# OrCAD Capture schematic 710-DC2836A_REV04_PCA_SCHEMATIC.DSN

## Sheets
1 PAGE3
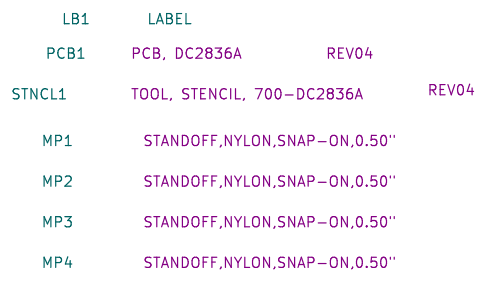
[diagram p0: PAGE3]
2 PAGE1: size Custom; title: SWITCHER WITH DIGITAL POWER SYSTEM MANAGEMENT; company: ANALOG DEVICES; note: DEMO BOARD BILL OF MATERIALS; note: DUAL 6A 20V POLYPHASE MONOLITHIC STEP-DOWN SILENT
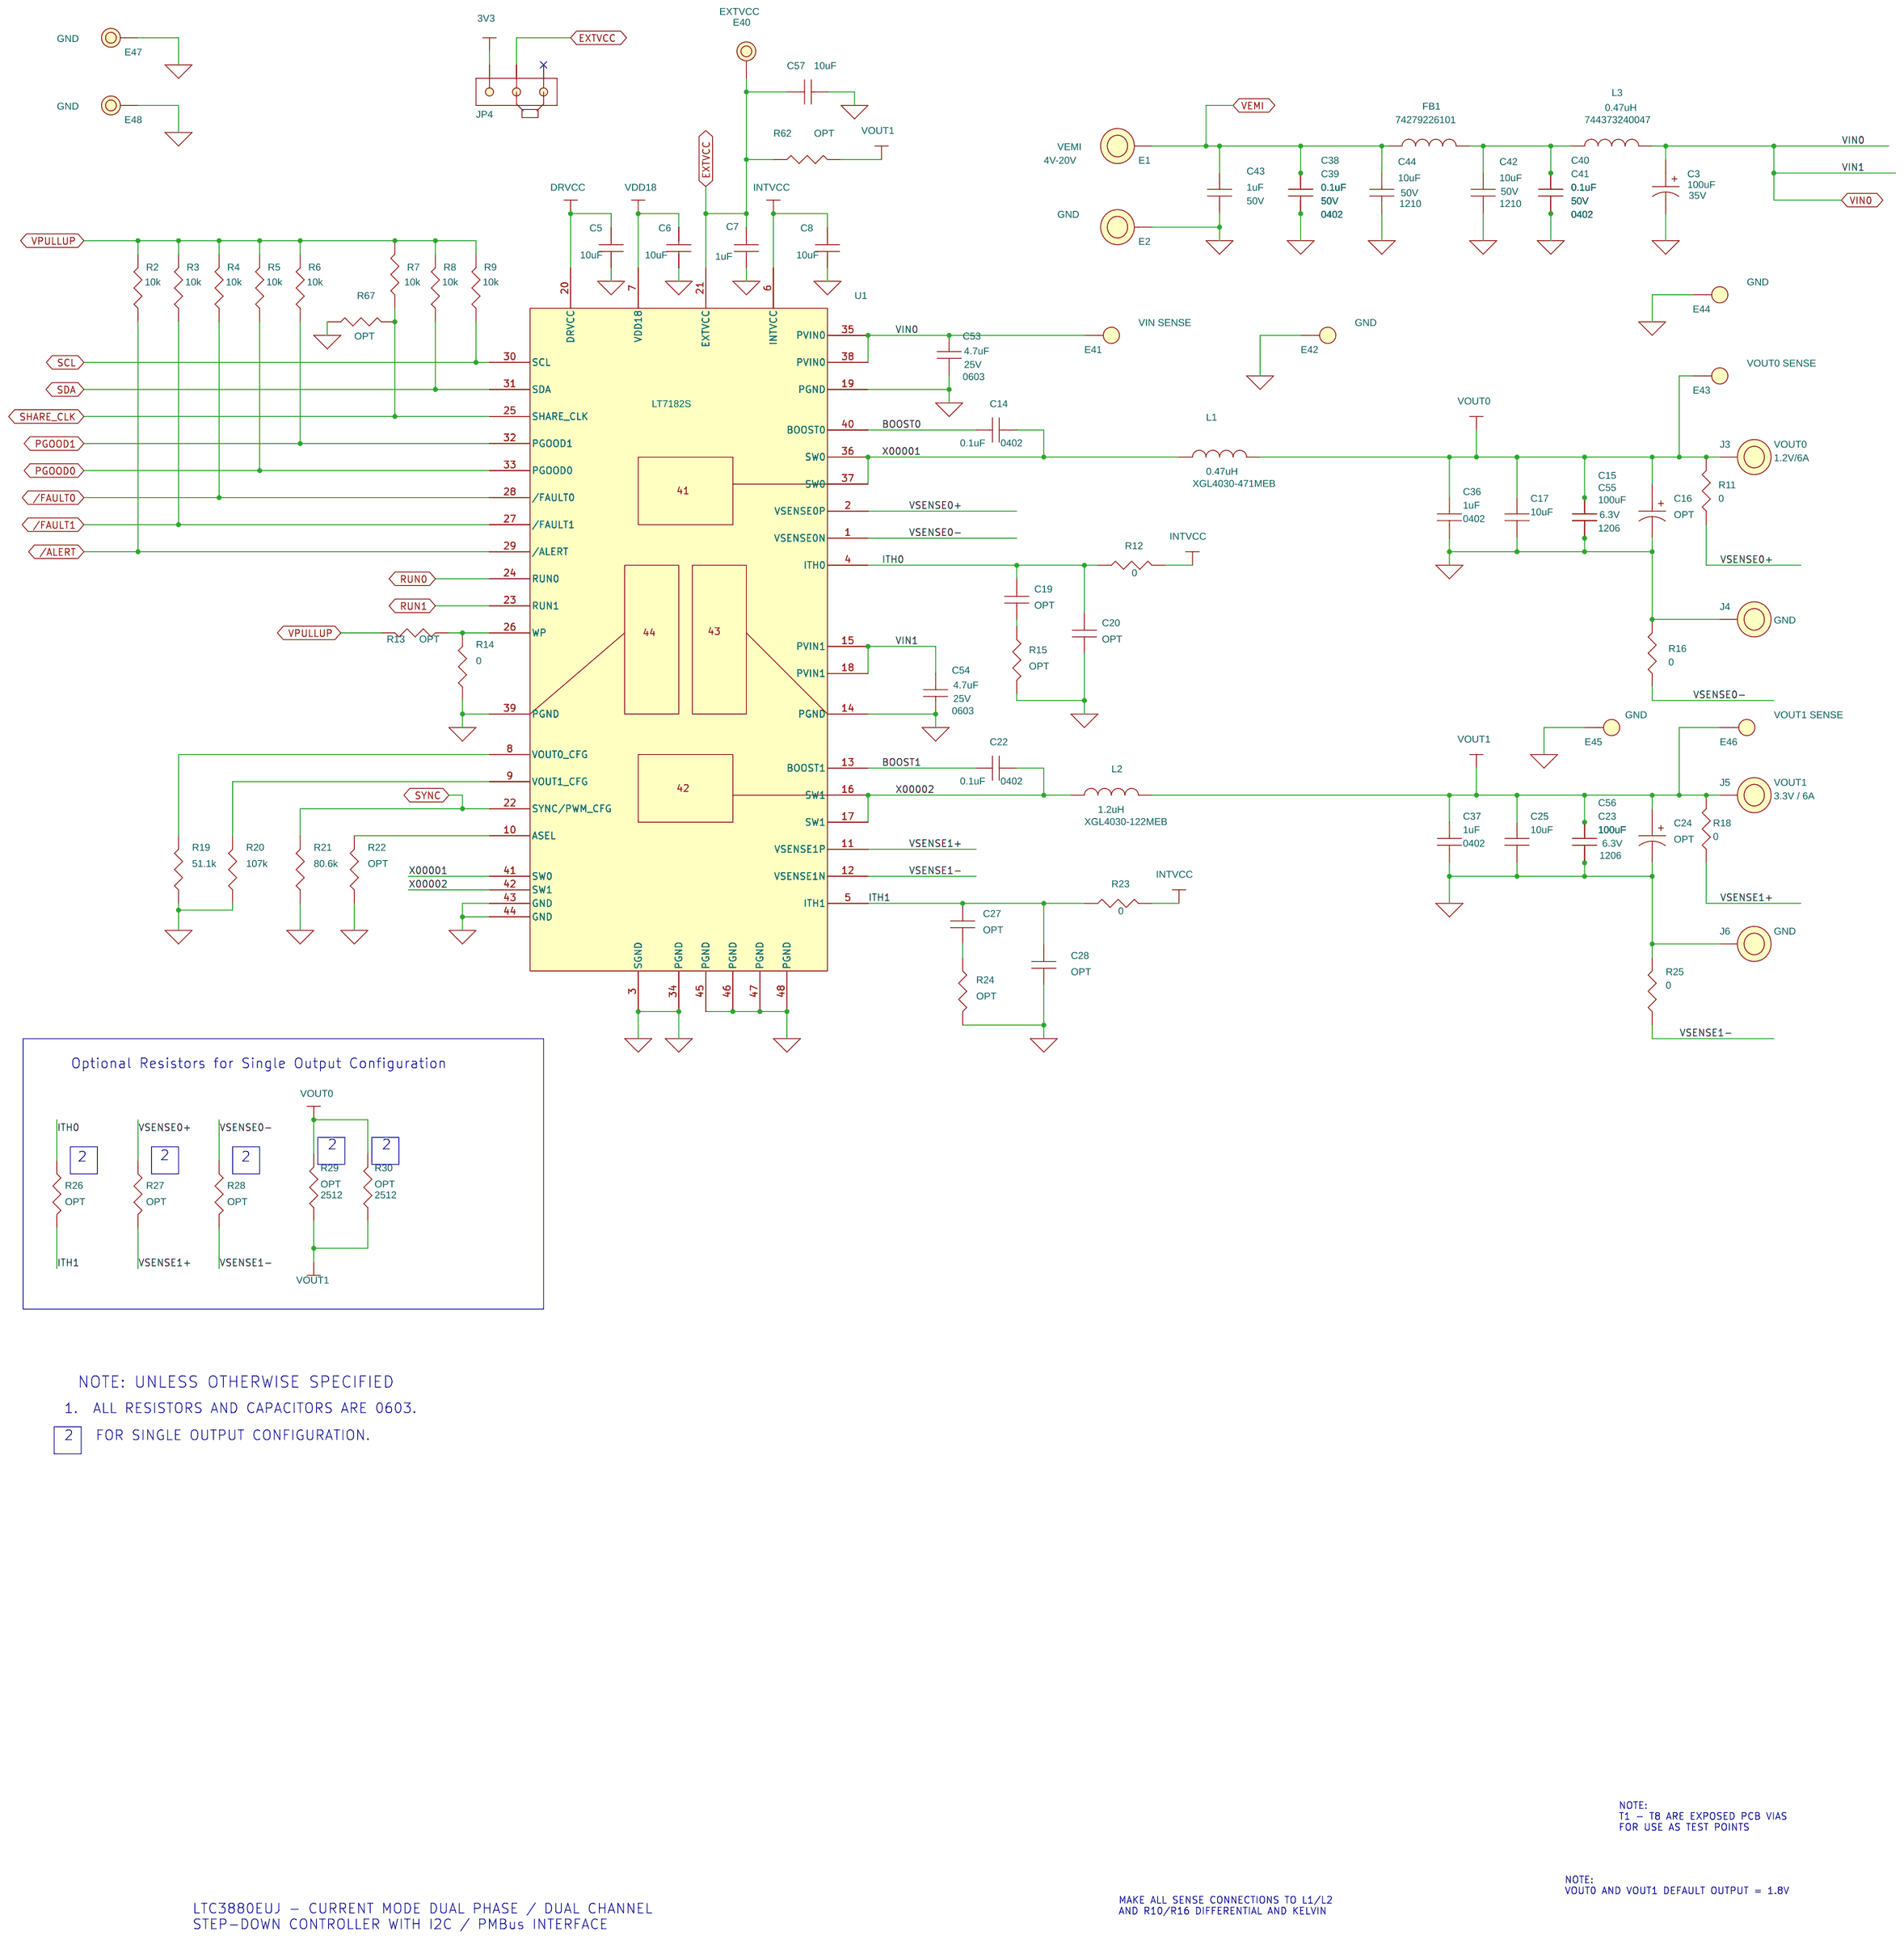
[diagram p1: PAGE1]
3 PAGE2: size Custom; title: SWITCHER WITH DIGITAL POWER SYSTEM MANAGEMENT; company: ANALOG DEVICES; note: DEMO BOARD BILL OF MATERIALS; note: DUAL 6A 20V POLYPHASE MONOLITHIC STEP-DOWN SILENT
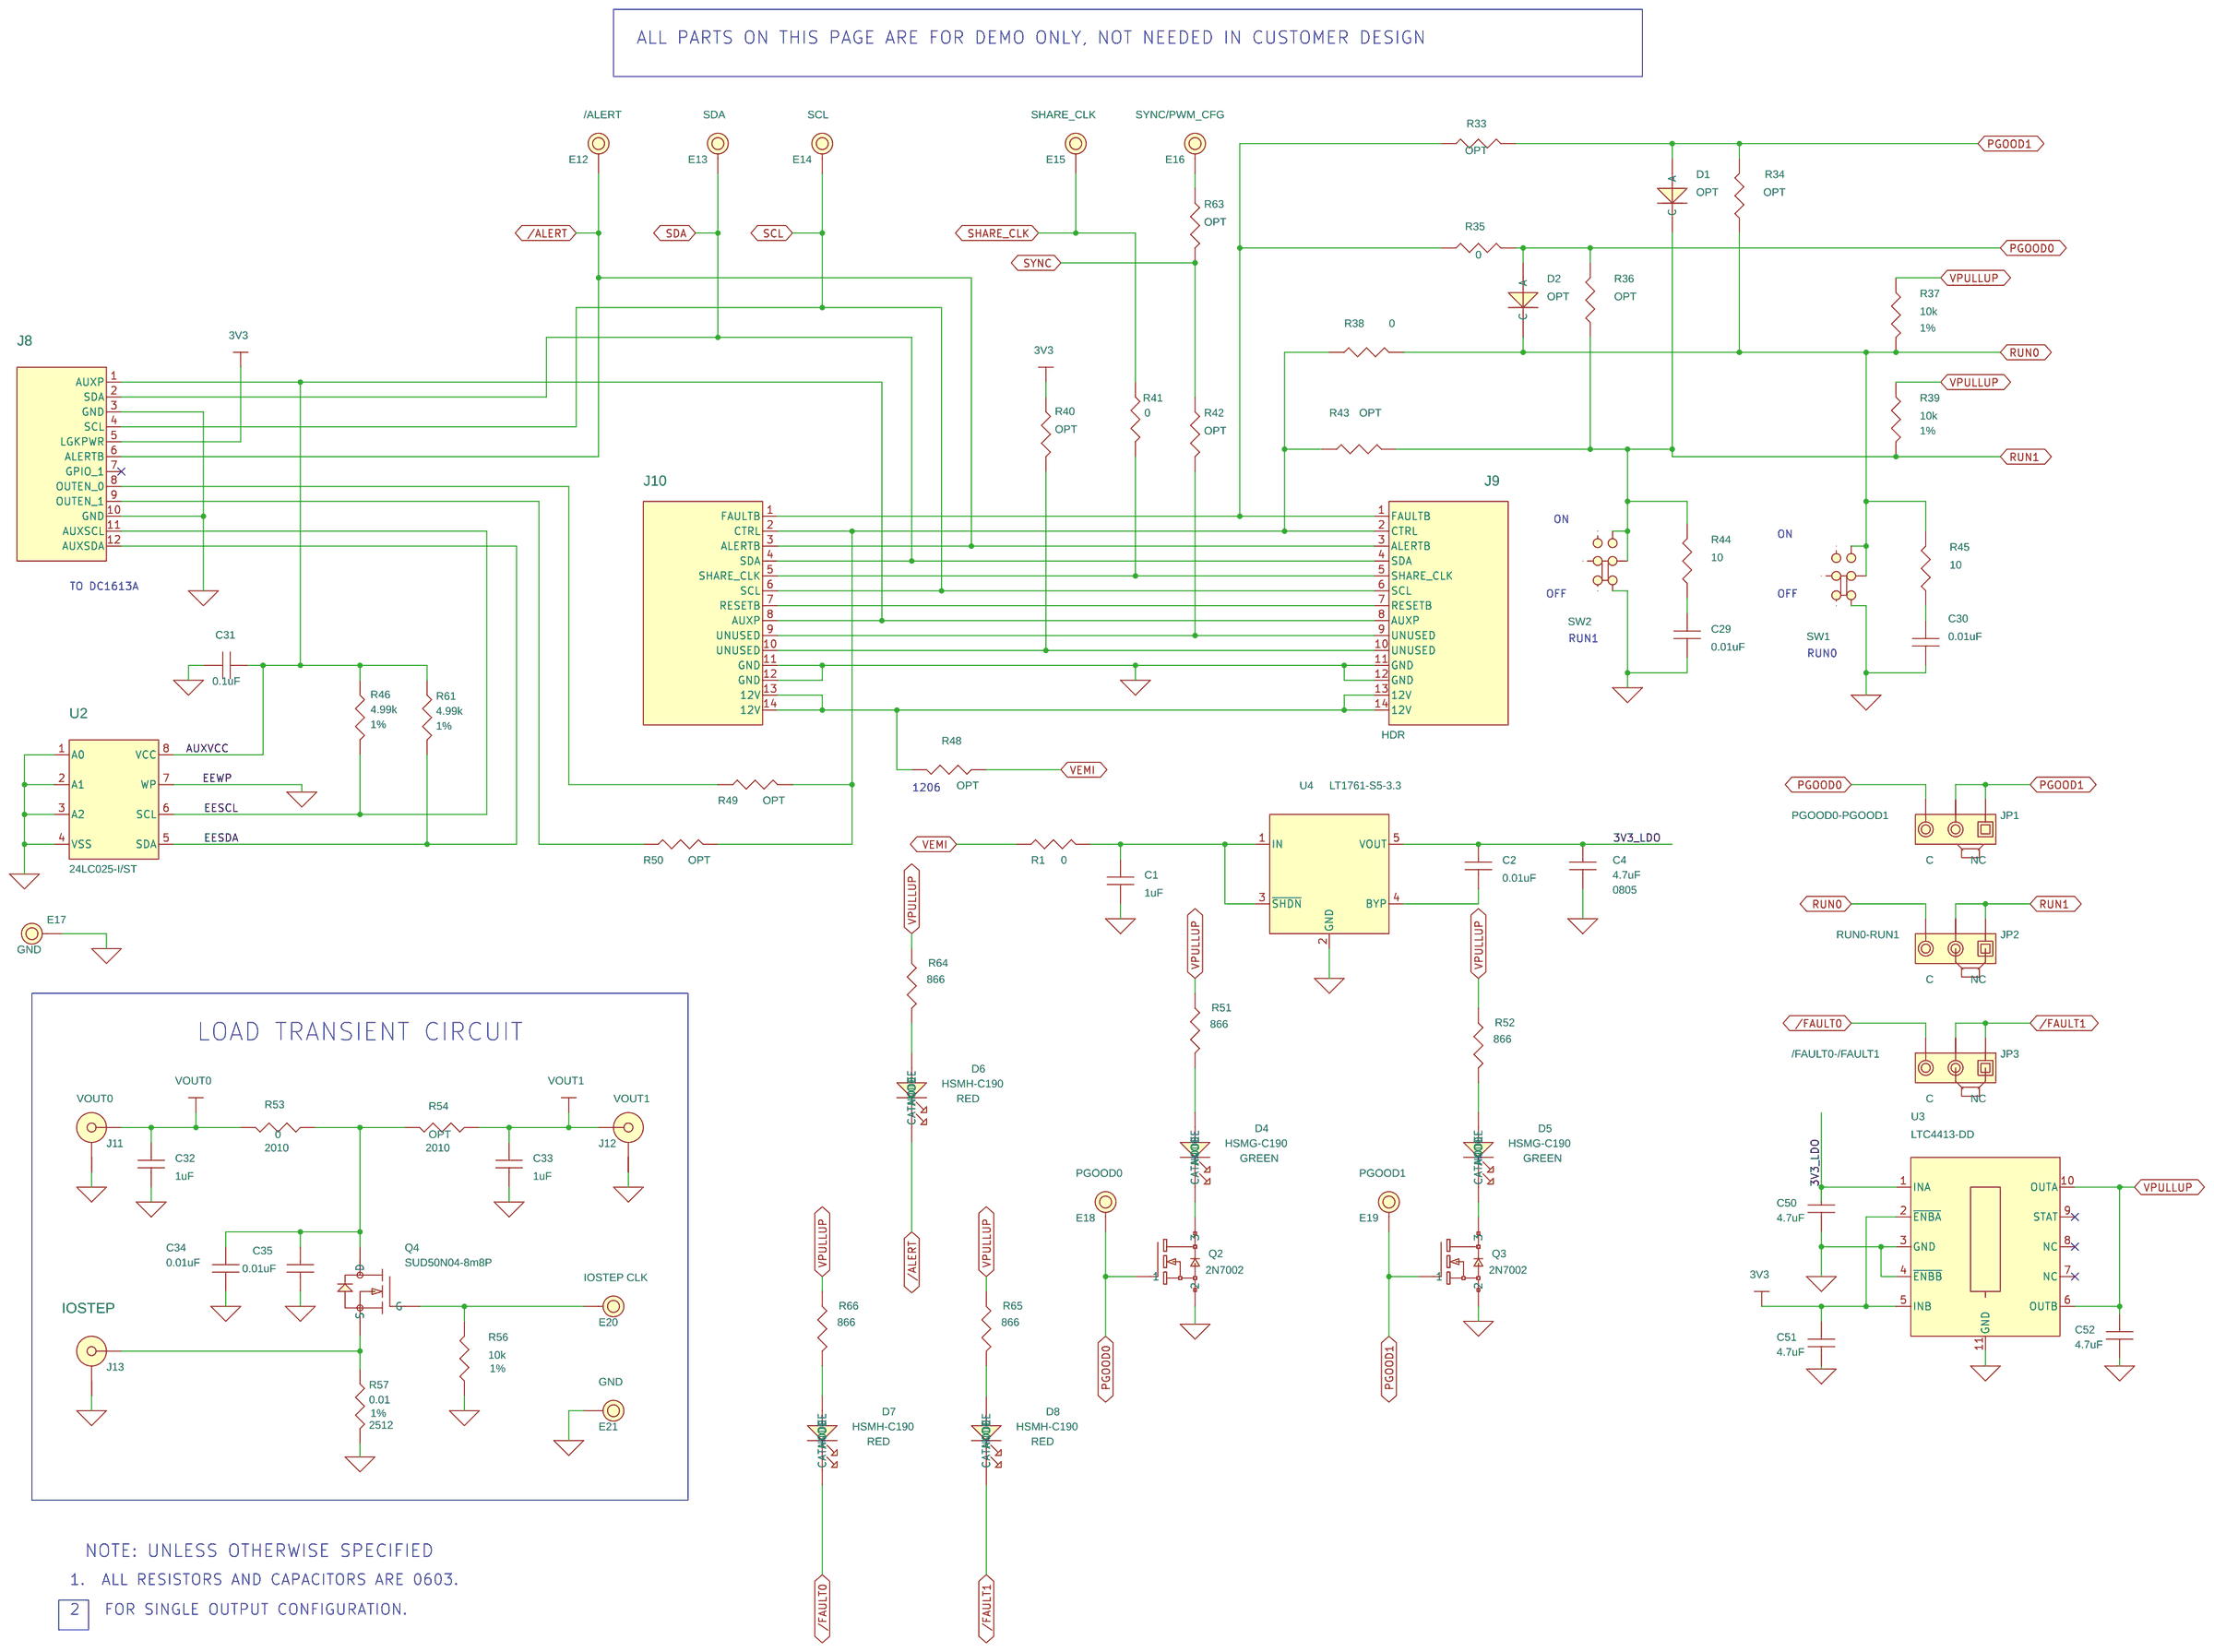
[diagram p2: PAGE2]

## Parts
sheet PAGE1
C3  100uF  [PANASONIC_ZK_6.3X7.7]
C5  10uF  [CC0603N]
C6  10uF  [CC0603N]
C7  1uF  [CC0603N]
C8  10uF  [CC0603N]
C14  0.1uF  [CC0402N]
C15  100uF  [CC1206N]
C16  OPT  [CAPMP7343N]
C17  10uF  [CC0603N]
C19  OPT  [CC0603N]
C20  OPT  [CC0603N]
C22  0.1uF  [CC0402N]
C23  100uF  [CC1206N]
C24  OPT  [CAPMP7343N]
C25  10uF  [CC0603N]
C27  OPT  [CC0603N]
C28  OPT  [CC0603N]
C36  1uF  [CC0402N]
C37  1uF  [CC0402N]
C38  0.1uF  [CC0402N]
C39  0.1uF  [CC0402N]
C40  0.1uF  [CC0402N]
C41  0.1uF  [CC0402N]
C42  10uF  [CC1210N]
C43  1uF  [CC0603N]
C44  10uF  [CC1210N]
C53  4.7uF  [CC0603N]
C54  4.7uF  [CC0603N]
C55  100uF  [CC1206N]
C56  100uF  [CC1206N]
C57  10uF  [CC0603N]
E1  BANANA JACK  [KEY-575-4]
E2  BANANA JACK  [KEY-575-4]
E40  TEST POINT  [MILLMAX2501]
E41  TEST POINT  [MILLMAX2308]
E42  TEST POINT  [MILLMAX2308]
E43  TEST POINT  [MILLMAX2308]
E44  TEST POINT  [MILLMAX2308]
E45  TEST POINT  [MILLMAX2308]
E46  TEST POINT  [MILLMAX2308]
E47  TEST POINT  [MILLMAX2501]
E48  TEST POINT  [MILLMAX2501]
FB1  100 OHMS@100MHz  [WURTH-74279226101]
J3  BANANA JACK  [KEY-575-4]
J4  BANANA JACK  [KEY-575-4]
J5  BANANA JACK  [KEY-575-4]
J6  BANANA JACK  [KEY-575-4]
JP4  HDR  [HD1X3-079]
L1  0.47uH  [COILCRAFT-XGL4030]
L2  1.2uH  [COILCRAFT-XGL4030]
L3  0.47uH  [WURTH-4020]
R2  10k  [CR0603N]
R3  10k  [CR0603N]
R4  10k  [CR0603N]
R5  10k  [CR0603N]
R6  10k  [CR0603N]
R7  10k  [CR0603N]
R8  10k  [CR0603N]
R9  10k  [CR0603N]
R11  0  [CR0603N]
R12  0  [CR0603N]
R13  OPT  [CR0603N]
R14  0  [CR0603N]
R15  OPT  [CR0603N]
R16  0  [CR0603N]
R18  0  [CR0603N]
R19  51.1k  [CR0603N]
R20  107k  [CR0603N]
R21  80.6k  [CR0603N]
R22  OPT  [CR0603N]
R23  0  [CR0603N]
R24  OPT  [CR0603N]
R25  0  [CR0603N]
R26  OPT  [CR0603N]
R27  OPT  [CR0603N]
R28  OPT  [CR0603N]
R29  OPT  [CR2512N]
R30  OPT  [CR2512N]
R62  OPT  [CR0603N]
R67  OPT  [CR0603N]
U1  LT7182S  [LTC-LQFN-40-1607]
XJP4  SHUNT
sheet PAGE2
C1  1uF  [CC0603N]
C2  0.01uF  [CC0603N]
C4  4.7uF  [CC0805N]
C29  0.01uF  [CC0603N]
C30  0.01uF  [CC0603N]
C31  0.1uF  [CC0603N]
C32  1uF  [CC0603N]
C33  1uF  [CC0603N]
C34  0.01uF  [CC0603N]
C35  0.01uF  [CC0603N]
C50  4.7uF  [CC0603N]
C51  4.7uF  [CC0603N]
C52  4.7uF  [CC0603N]
D1  OPT  [SOD-323N]
D2  OPT  [SOD-323N]
D4  GREEN  [LED_0603]
D5  GREEN  [LED_0603]
D6  RED  [LED_0603]
D7  RED  [LED_0603]
D8  RED  [LED_0603]
E12  TEST POINT  [MILLMAX2501]
E13  TEST POINT  [MILLMAX2501]
E14  TEST POINT  [MILLMAX2501]
E15  TEST POINT  [MILLMAX2501]
E16  TEST POINT  [MILLMAX2501]
E17  TEST POINT  [MILLMAX2501]
E18  TEST POINT  [MILLMAX2501]
E19  TEST POINT  [MILLMAX2501]
E20  TEST POINT  [MILLMAX2501]
E21  TEST POINT  [MILLMAX2501]
J8  HDR,SHROUDED  [HD2X6-079-MOLEX]
J9  HDR  [MOLEX-0877601416]
J10  HDR  [SULLINS-NPPN072FJFN-RC]
J11  RF,BNC  [CONNEX-112404]
J12  RF,BNC  [CONNEX-112404]
J13  RF,BNC  [CONNEX-112404]
JP1  HDR  [HD1X3-079]
JP2  HDR  [HD1X3-079]
JP3  HDR  [HD1X3-079]
Q2  2N7002  [SOT23-3N]
Q3  2N7002  [SOT23-3N]
Q4  SUD50N04-8m8P  [TO-252-3N]
R1  0  [CR0603N]
R33  OPT  [CR0603N]
R34  OPT  [CR0603N]
R35  0  [CR0603N]
R36  OPT  [CR0603N]
R37  10k  [CR0603N]
R38  0  [CR0603N]
R39  10k  [CR0603N]
R40  OPT  [CR0603N]
R41  0  [CR0603N]
R42  OPT  [CR0603N]
R43  OPT  [CR0603N]
R44  10  [CR0603N]
R45  10  [CR0603N]
R46  4.99k  [CR0603N]
R48  OPT  [CR1206N]
R49  OPT  [CR0603N]
R50  OPT  [CR0603N]
R51  866  [CR0603N]
R52  866  [CR0603N]
R53  0  [CR2010N]
R54  OPT  [CR2010N]
R56  10k  [CR0603N]
R57  0.01  [VISHAY-WSL2512-T30]
R61  4.99k  [CR0603N]
R63  OPT  [CR0603N]
R64  866  [CR0603N]
R65  866  [CR0603N]
R66  866  [CR0603N]
SW1  DPDT  [CK-JS202011CQN]
SW2  DPDT  [CK-JS202011CQN]
U2  24LC025-I/ST  [MICROCHIP-TSSOP-8]
U3  LTC4413-DD  [LTC-DD-10-1699]
U4  LT1761-S5-3.3  [LTC-S5-5-1635]
XJP1  SHUNT
XJP2  SHUNT
XJP3  SHUNT
sheet PAGE3
LB1  LABEL  [895-0154_REV01]
MP1  STANDOFF  [KEYSTONE_8829-8834]
MP2  STANDOFF  [KEYSTONE_8829-8834]
MP3  STANDOFF  [KEYSTONE_8829-8834]
MP4  STANDOFF  [KEYSTONE_8829-8834]
PCB1  PCB, DC2836A
STNCL1  TOOL, STENCIL, 700-DC2836A

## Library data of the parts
C3 = CAP_P: CAP.,100uF,ALUM,35V,20%,SMD,AEC-Q200; CLASS: DISCRETE; Dielectric Type: ALUM; Inventory Qty: 0; Manufacturer: PANASONIC; Manufacturer PN: EEHZK1V101XP; PART_NUMBER: 150-1440; Package Size: SMD; Part Number: PANASONIC EEHZK1V101XP; Rated Voltage: 35V; Tolerance: 20%
C5 C6 C8 C57 = CAP: CAP.,10uF,X6S,10V,10%,0603,Interposer Termination,NO SUBS ALLOWED; CLASS: DISCRETE; Dielectric Type: X6S; FPLIST: CC0603N,CC0603L,CC0603M; Inventory Qty: 0; Manufacturer: MURATA; Manufacturer PN: ZRB18AC81A106KE01L; PART_NUMBER: 150-0797; Package Size: 0603; Part Number: MURATA ZRB18AC81A106KE01L; Rated Voltage: 10V; Tolerance: 10%
C7 = CAP: CAP.,1uF,X7R,16V,10%,0603; CLASS: DISCRETE; Dielectric Type: X7R; FPLIST: CC0603N,CC0603L,CC0603M; Inventory Qty: 29099; Manufacturer: KEMET; Manufacturer PN: C0603C105K4RAC7867; PART_NUMBER: 150-0179; Package Size: 0603; Part Number: MURATA ZRB18AC81A106KE01L; Rated Voltage: 16V; Tolerance: 10%
C14 C22 = CAP: CAP.,0.1uF,X7R,25V,10%,0402,NO SUBS ALLOWED; CLASS: DISCRETE; Component: cap; Dielectric Type: X7R; FPLIST: CC0402N,CC0402L,CC0402M; Inventory Qty: 275; Manufacturer: MURATA; Manufacturer PN: GRM155R71E104KE14; PART_NUMBER: 150-0441; Package Size: 0402; Part Number: AVX 04023D104KAT2A; Rated Voltage: 25V; Temperature Coefficient: X7R; Tolerance: 10%
C15 C23 C55 C56 = CAP: CAP.,100uF,X5R,6.3V,10%,1206; CLASS: DISCRETE; Dielectric Type: X5R; FPLIST: CC1206N,CC1206L,CC1206M; Inventory Qty: 5866; Manufacturer: MURATA; Manufacturer PN: GRM31CR60J107KE39L; PART_NUMBER: 150-2327; Package Size: 1206; Part Number: MURATA GRM31CR60J107KE39L; Rated Voltage: 6.3V; Tolerance: 10%
C16 C24 = CAP_P: CAP., OPTION, 7343; CLASS: DISCRETE; FPLIST: CAPMP7343N,CAPMP7343L,CAPMP7343M; PART_NUMBER: 150-0067; Package Size: 7343; Package Type: SMD; Part Number: OPTION
C17 C25 = CAP: CAP.,10uF,X5R,10V,10%,0603; CLASS: DISCRETE; Dielectric Type: X5R; FPLIST: CC0603N,CC0603L,CC0603M; Inventory Qty: 23010; Manufacturer: AVX; Manufacturer PN: 0603ZD106KAT2A; PART_NUMBER: 150-0576; Package Size: 0603; Part Number: AVX 12106D107KAT2A; Rated Voltage: 10V; Tolerance: 10%
C19 C20 C27 C28 = CAP: CAP., OPTION, 0603; CLASS: DISCRETE; Component: cap; FPLIST: CC0603N,CC0603L,CC0603M; PART_NUMBER: 150-3038; Package Size: 0603; Package Type: SMD; Part Number: OPTION
C36 C37 = CAP: CAP.,1uF,X5R,35V,10%,0402; CLASS: DISCRETE; Dielectric Type: X5R; FPLIST: CC0402N, CC0402M,CC0402L; Inventory Qty: 9244; Manufacturer: MURATA; Manufacturer PN: GRM155R6YA105KE11D; PART_NUMBER: 150-0652; Package Size: 0402; Package Type: Surface Mount, MLCC; Part Number: AVX 12106D107KAT2A; Rated Voltage: 35V; Temperature Coefficient: X5R; Tolerance: 10%
C38-C41 = CAP: CAP.,0.1uF,X7R,50V,10%,0402,AEC-Q200, NO SUBS. ALLOWED; CLASS: DISCRETE; Dielectric Type: X7R; FPLIST: CC0402N,CC0402L,CC0402M; Inventory Qty: 11376; Manufacturer: MURATA; Manufacturer PN: GCM155R71H104KE02D; PART_NUMBER: 150-2353; Package Size: 0402; Part Number: MURATA GCM155R71H104KE02D; Rated Voltage: 50V; Tolerance: 10%
C42 C44 = CAP: CAP.,10uF,X5R,50V,10%,1210; CLASS: DISCRETE; Dielectric Type: X5R; FPLIST: CC1210N,CC1210L,CC1210M; Inventory Qty: 14956; Manufacturer: TDK; Manufacturer PN: C3225X5R1H106K250AB; PART_NUMBER: 150-3288; Package Size: 1210; Part Number: TDK C3225X5R1H106K250AB; Rated Voltage: 50V; Tolerance: 10%
C43 = CAP: CAP.,1uF,X5R,50V,10%,0603,AEC-Q200; CLASS: DISCRETE; Dielectric Type: X5R; FPLIST: CC0603N,CC0603L,CC0603M; Inventory Qty: 52068; Manufacturer: TAIYO YUDEN; Manufacturer PN: UMK107ABJ105KAHT; PART_NUMBER: 150-2446; Package Size: 0603; Package Type: SMD; Part Number: TDK CGA3E3X5R1H105K080AB; Rated Voltage: 50V; Tolerance: 10%
C53 C54 = CAP: CAP.,4.7uF,X6S,25V,10%,0603; CLASS: DISCRETE; Component: cap; Dielectric Type: X6S; FPLIST: CC0603N,CC0603L,CC0603M; Inventory Qty: 0; Manufacturer: MURATA; Manufacturer PN: GRM188C81E475KE11D; PART_NUMBER: 150-0798; Package Size: 0603; Part Number: TDK C3216X5R1E476M160AC; Part Type: CAP1206; Rated Voltage: 25V; Tolerance: 10%
E1 = BANANA_KEYSTONE-575-4: CONN.,BANANA JACK,FEMALE,THT,NON-INSULATED,SWAGE,0.218"; 1ST PART FIELD: 4V-20V; 2nd Part Field: VEMI; CLASS: IO; Inventory Qty: 203061; Manufacturer: KEYSTONE; Manufacturer PN: 575-4; PART_NUMBER: 250-0428
E2 = BANANA_KEYSTONE-575-4: CONN.,BANANA JACK,FEMALE,THT,NON-INSULATED,SWAGE,0.218"; 1ST PART FIELD: GND; CLASS: IO; Inventory Qty: 203061; Manufacturer: KEYSTONE; Manufacturer PN: 575-4; PART_NUMBER: 250-0428
E40 = TESTPOINT_.219_MILL-MAX_2501: TEST POINT,TURRET,0.094" MTG. HOLE,PCB 0.062" THK; CLASS: IO; Inventory Qty: 823526; Manufacturer: MILL-MAX; Manufacturer PN: 2501-2-00-80-00-00-07-0; PART_FIELD_01: EXTVCC; PART_NUMBER: 260-0003; Part Number: MILL-MAX 2501-2-00-80-00-00-07-0
E41 = TEST_POINT_.156_MILL-MAX_2308: TEST POINT,TURRET,0.064" MTG. HOLE,PCB 0.062" THK; CLASS: IO; FPLIST: MILLMAX2308,MILLMAX2308-2; Inventory Qty: 1142083; Manufacturer: MILL-MAX; Manufacturer PN: 2308-2-00-80-00-00-07-0; PART_FIELD_1: VIN SENSE; PART_NUMBER: 260-0004
E42 E44 E45 = TEST_POINT_.156_MILL-MAX_2308: TEST POINT,TURRET,0.064" MTG. HOLE,PCB 0.062" THK; CLASS: IO; FPLIST: MILLMAX2308,MILLMAX2308-2; Inventory Qty: 1142083; Manufacturer: MILL-MAX; Manufacturer PN: 2308-2-00-80-00-00-07-0; PART_FIELD_1: GND; PART_NUMBER: 260-0004
E43 = TEST_POINT_.156_MILL-MAX_2308: TEST POINT,TURRET,0.064" MTG. HOLE,PCB 0.062" THK; CLASS: IO; FPLIST: MILLMAX2308,MILLMAX2308-2; Inventory Qty: 1142083; Manufacturer: MILL-MAX; Manufacturer PN: 2308-2-00-80-00-00-07-0; PART_FIELD_1: VOUT0 SENSE; PART_NUMBER: 260-0004
E46 = TEST_POINT_.156_MILL-MAX_2308: TEST POINT,TURRET,0.064" MTG. HOLE,PCB 0.062" THK; CLASS: IO; FPLIST: MILLMAX2308,MILLMAX2308-2; Inventory Qty: 1142083; Manufacturer: MILL-MAX; Manufacturer PN: 2308-2-00-80-00-00-07-0; PART_FIELD_1: VOUT1 SENSE; PART_NUMBER: 260-0004
E17 E21 E47 E48 = TESTPOINT_.219_MILL-MAX_2501: TEST POINT,TURRET,0.094" MTG. HOLE,PCB 0.062" THK; CLASS: IO; Inventory Qty: 823526; Manufacturer: MILL-MAX; Manufacturer PN: 2501-2-00-80-00-00-07-0; PART_FIELD_01: GND; PART_NUMBER: 260-0003; Part Number: MILL-MAX 2501-2-00-80-00-00-07-0
FB1 = IND: IND.,100 OHMS@100MHz,FERRITE BEAD,25%,8A,6mOHMS,1812; CLASS: DISCRETE; Inventory Qty: 3043; Manufacturer: WURTH ELEKTRONIK; Manufacturer PN: 74279226101; PART_NUMBER: 200-0280; Package Size: 1812; Part Number: WURTH ELEKTRONIK 74279226101; Tolerance: 25%
J3 = BANANA_KEYSTONE-575-4: CONN.,BANANA JACK,FEMALE,THT,NON-INSULATED,SWAGE,0.218"; CLASS: IO; Inventory Qty: 203061; Manufacturer: KEYSTONE; Manufacturer PN: 575-4; PART_FIELD_01: VOUT0; PART_NUMBER: 250-0428; Part_Field_02: 1.2V/6A
J4 J6 = BANANA_KEYSTONE-575-4: CONN.,BANANA JACK,FEMALE,THT,NON-INSULATED,SWAGE,0.218"; CLASS: IO; Inventory Qty: 203061; Manufacturer: KEYSTONE; Manufacturer PN: 575-4; PART_FIELD_01: GND; PART_NUMBER: 250-0428; Part Number: MILL-MAX 2501-2-00-80-00-00-07-0
J5 = BANANA_KEYSTONE-575-4: CONN.,BANANA JACK,FEMALE,THT,NON-INSULATED,SWAGE,0.218"; CLASS: IO; Inventory Qty: 203061; Manufacturer: KEYSTONE; Manufacturer PN: 575-4; PART_FIELD_01: VOUT1; PART_NUMBER: 250-0428; Part Number: MILL-MAX 2501-2-00-80-00-00-07-0; Part_Field_02: 3.3V / 6A
JP4 = 1X3: CONN.,HDR,MALE,1x3,2mm,VERT,ST,THT,NO SUBS. ALLOWED; CLASS: IO; Inventory Qty: 28997; Manufacturer: Wurth Elektronik; Manufacturer PN: 62000311121; PART_NUMBER: 250-0639
L1 = IND: IND.,0.47uH,PWR,20%,21.2A,3.4mOHMS,SMD,AEC-Q200,SHIELDED; CLASS: DISCRETE; Inventory Qty: 0; Manufacturer: COILCRAFT; Manufacturer PN: XGL4030-471MEB; PART_NUMBER: 200-0406; Package Size: SMD; Tolerance: 20%
L2 = IND: IND.,1.2uH,PWR,20%,12.2A,9.4mOHMS,SMD,AEC-Q200,SHIELDED; CLASS: DISCRETE; Inventory Qty: 0; Manufacturer: COILCRAFT; Manufacturer PN: XGL4030-122MEB; PART_NUMBER: 200-0407; Package Size: SMD; Tolerance: 20%
L3 = IND: IND.,0.47uH,PWR,20%,6.8A,14mOHMS,SMD,SHIELDED; CLASS: DISCRETE; Inventory Qty: 0; Manufacturer: WURTH ELEKTRONIK; Manufacturer PN: 744373240047; PART_NUMBER: 200-0408; Package Size: SMD; Tolerance: 20%
R2-R9 = RES: RES.,10k OHMS,1%,1/10W,0603,AEC-Q200; CLASS: DISCRETE; FPLIST: CR0603N,CR0603L,CR0603M; Inventory Qty: 194448; Manufacturer: VISHAY; Manufacturer PN: CRCW060310K0FKEA; PART_NUMBER: 100-2012; Package Size: 0603; Part Number: VISHAY CRCW060310K0FKEA; Part Type: CR0402; Rated Power: 1/10W; Temperature Coefficient: +/-100ppm/C; Tolerance: 1%
R11 R12 R14 R16 R18 R23 R25 R35 R38 R41 = RES: RES.,0 OHM,1/10W,0603,AEC-Q200; CLASS: DISCRETE; FPLIST: CR0603N,CR0603L,CR0603M; Inventory Qty: 680122; Manufacturer: VISHAY; Manufacturer PN: CRCW06030000Z0EA; PART_NUMBER: 100-0009; Package Size: 0603; Part Number: VISHAY CRCW06030000Z0EA; Rated Power: 1/10W
R13 R15 R24 R26-R28 R33 R34 R36 R40 R42 R43 R49 R50 R62 R63 R67 = RES: RES., OPTION, 0603; CLASS: DISCRETE; FPLIST: CR0603N,CR0603L,CR0603M; PART_NUMBER: 100-2374; Package Size: 0603; Part Number: OPTION
R19 = RES: RES.,51.1k OHMS,1%,1/10W,0603,AEC-Q200; CLASS: DISCRETE; FPLIST: CR0603N,CR0603L,CR0603M; Inventory Qty: 84370; Manufacturer: PANASONIC; Manufacturer PN: ERJ3EKF5112V; PART_NUMBER: 100-0508; Package Size: 0603; Part Number: TBD; Part Type: CR0402; Rated Power: 1/10W; Temperature Coefficient: 100ppm; Tolerance: 1%
R20 = RES: RES.,107k OHMS,1%,1/10W,0603,AEC-Q200; CLASS: DISCRETE; FPLIST: CR0603N,CR0603L,CR0603M; Inventory Qty: 97918; Manufacturer: NIC; Manufacturer PN: NRC06F1073TRF; PART_NUMBER: 100-2103; Package Size: 0603; Part Number: TBD; Part Type: CR0402; Rated Power: 1/10W; Temperature Coefficient: +/-100ppm; Tolerance: 1%
R21 = RES: RES.,80.6k OHMS,1%,1/10W,0603; CLASS: DISCRETE; FPLIST: CR0603N,CR0603L,CR0603M; Inventory Qty: 56958; Manufacturer: VISHAY; Manufacturer PN: CRCW060380K6FKEA; PART_NUMBER: 100-2503; Package Size: 0603; Part Number: TBD; Part Type: CR0402; Rated Power: 1/10W; Temperature Coefficient: 100ppm/C; Tolerance: 1%
R22 = RES: RES., OPTION, 0603; BOM Notes: TBD; CLASS: DISCRETE; FPLIST: CR0603N,CR0603L,CR0603M; PART_NUMBER: 100-2374; Package Size: 0603; Part Number: TBD; Part Type: CR0402
R29 R30 = RES: RES., OPTION, 2512; CLASS: DISCRETE; FPLIST: CR2512N,CR2512L,CR2512M; PART_NUMBER: 100-2376; Package Size: 2512; Part Number: OPTION
U1 = LT7182S: IC,6A,20V DUAL-OUTPUT POLYPHASE MONOLITHIC STEP-DOWN SWITCHER,LQFN-40; CLASS: IC; Inventory Qty: 0; Manufacturer: ANALOG DEVICES; Manufacturer PN: LT7182SRV#PBF; PART_NUMBER: LT7182SRV#PBF; Package Size: 7mmX5mmX0.9; Package Type: LQFN-40; Rated Power: 20V
XJP1-XJP4 = SHUNT_2MM: CONN.,SHUNT,FEMALE,2-POS,2mm; CLASS: IO; Inventory Qty: 64675; Manufacturer: Wurth Elektronik; Manufacturer PN: 60800213421; PART_NUMBER: 250-0485; Part Number: Wurth Elektronik 60800213421
C1 = CAP: CAP.,1uF,X5R,50V,10%,0603; CLASS: DISCRETE; Dielectric Type: X5R; FPLIST: CC0603N,CC0603L,CC0603M; Inventory Qty: 11270; Manufacturer: AVX; Manufacturer PN: 06035D105KAT2A; PART_NUMBER: 150-3292; Package Size: 0603; Package Type: SMD; Part Number: MURATA GCM188R71H103KA37D; Rated Voltage: 50V; Tolerance: 10%
C2 = CAP: CAP.,0.01uF,X7R,25V,10%,0603; CLASS: DISCRETE; Dielectric Type: X7R; FPLIST: CC0603N,CC0603L,CC0603M; Inventory Qty: 1100; Manufacturer: TDK; Manufacturer PN: C1608X7R1E103K080AA; PART_NUMBER: 150-0299; Package Size: 0603; Part Number: MURATA GCM188R71H103KA37D; Rated Voltage: 25V; Tolerance: 10%
C4 = CAP: CAP.,4.7uF,X7R,10V,10%,0805; CLASS: DISCRETE; Dielectric Type: X7R; FPLIST: CC0805N,CC0805L,CC0805M; Inventory Qty: 5296; Manufacturer: AVX; Manufacturer PN: 0805ZC475KAT2A; PART_NUMBER: 150-3418; Package Size: 0805; Part Number: MURATA GCM188R71H103KA37D; Rated Voltage: 10V; Tolerance: 10%
C29 C30 = CAP: CAP.,0.01uF,X5R,25V,10%,0603; CLASS: DISCRETE; Dielectric Type: X5R; FPLIST: CC0603N,CC0603L,CC0603M; Inventory Qty: 19860; Manufacturer: AVX; Manufacturer PN: 06033D103KAT2A; PART_NUMBER: 150-2324; Package Size: 0603; Part Number: AVX 06033C103KAT2A; Rated Voltage: 25V; Tolerance: 10%
C31 = CAP: CAP.,0.1uF,X7R,10V,20%,0603; CLASS: DISCRETE; Dielectric Type: X7R; FPLIST: CC0603N,CC0603L,CC0603M; Inventory Qty: 17762; Manufacturer: AVX; Manufacturer PN: 0603ZC104MAT2A; PART_NUMBER: 150-3258; Package Size: 0603; Part Number: AVX 0603ZC104MAT2A; Rated Voltage: 10V; Tolerance: 20%
C32 C33 = CAP: CAP.,1uF,X5R,10V,10%,0603; CLASS: DISCRETE; Dielectric Type: X5R; FPLIST: CC0603N,CC0603L,CC0603M; Inventory Qty: 36821; Manufacturer: MURATA; Manufacturer PN: GRM188R61A105KA61D; PART_NUMBER: 150-0113; Package Size: 0603; Part Number: MURATA GCM188R71H103KA37D; Rated Voltage: 10V; Tolerance: 10%
C34 C35 = CAP: CAP.,0.01uF,X5R,50V,10%,0603; CLASS: DISCRETE; Dielectric Type: X5R; FPLIST: CC0603N,CC0603L,CC0603M; Inventory Qty: 39774; Manufacturer: AVX; Manufacturer PN: 06035D103KAT2A; PART_NUMBER: 150-0049; Package Size: 0603; Part Number: MURATA GCM188R71H103KA37D; Rated Voltage: 50V; Tolerance: 10%
C50-C52 = CAP: CAP.,4.7uF,X5R,25V,10%,0603; CLASS: DISCRETE; Dielectric Type: X5R; FPLIST: CC0603N,CC0603L,CC0603M; Inventory Qty: 10846; Manufacturer: MURATA; Manufacturer PN: GRM188R61E475KE15D; PART_NUMBER: 150-0445; Package Size: 0603; Part Number: TDK C1608X7S0J475K080AC; Rated Voltage: 25V; Tolerance: 10%
D1 D2 = DIODE_A: DIODE, OPTION, SOD-323; CLASS: DISCRETE; FPLIST: SOD-323N,SOD-323L,SOD-323M; PART_NUMBER: 210-0118; Package Type: SOD-323; Part Number: OPTION
D4 D5 = LED: LED,GREEN,DIFFUSED,0603; CLASS: DISCRETE; Inventory Qty: 5000; Manufacturer: BROADCOM INC.; Manufacturer PN: HSMG-C190; PART_NUMBER: 270-0131; Package Type: 0603; Part Number: WURTH ELEK. 150060GS75000
D6-D8 = LED: LED,RED,DIFFUSED,0603; CLASS: DISCRETE; Inventory Qty: 4000; Manufacturer: BROADCOM INC.; Manufacturer PN: HSMH-C190; PART_NUMBER: 270-0156; Package Type: 0603; Part Number: WURTH ELEK. 150060GS75000
E12 = TESTPOINT_.219_MILL-MAX_2501: TEST POINT,TURRET,0.094" MTG. HOLE,PCB 0.062" THK; CLASS: IO; Inventory Qty: 823526; Manufacturer: MILL-MAX; Manufacturer PN: 2501-2-00-80-00-00-07-0; PART_FIELD_01: /ALERT; PART_NUMBER: 260-0003; Part Number: MILL-MAX 2501-2-00-80-00-00-07-0
E13 = TESTPOINT_.219_MILL-MAX_2501: TEST POINT,TURRET,0.094" MTG. HOLE,PCB 0.062" THK; CLASS: IO; Inventory Qty: 823526; Manufacturer: MILL-MAX; Manufacturer PN: 2501-2-00-80-00-00-07-0; PART_FIELD_01: SDA; PART_NUMBER: 260-0003; Part Number: MILL-MAX 2501-2-00-80-00-00-07-0
E14 = TESTPOINT_.219_MILL-MAX_2501: TEST POINT,TURRET,0.094" MTG. HOLE,PCB 0.062" THK; CLASS: IO; Inventory Qty: 823526; Manufacturer: MILL-MAX; Manufacturer PN: 2501-2-00-80-00-00-07-0; PART_FIELD_01: SCL; PART_NUMBER: 260-0003; Part Number: MILL-MAX 2501-2-00-80-00-00-07-0
E15 = TESTPOINT_.219_MILL-MAX_2501: TEST POINT,TURRET,0.094" MTG. HOLE,PCB 0.062" THK; CLASS: IO; Inventory Qty: 823526; Manufacturer: MILL-MAX; Manufacturer PN: 2501-2-00-80-00-00-07-0; PART_FIELD_01: SHARE_CLK; PART_NUMBER: 260-0003; Part Number: MILL-MAX 2501-2-00-80-00-00-07-0
E16 = TESTPOINT_.219_MILL-MAX_2501: TEST POINT,TURRET,0.094" MTG. HOLE,PCB 0.062" THK; CLASS: IO; Inventory Qty: 823526; Manufacturer: MILL-MAX; Manufacturer PN: 2501-2-00-80-00-00-07-0; PART_FIELD_01: SYNC/PWM_CFG; PART_NUMBER: 260-0003; Part Number: MILL-MAX 2501-2-00-80-00-00-07-0
E18 = TESTPOINT_.219_MILL-MAX_2501: TEST POINT,TURRET,0.094" MTG. HOLE,PCB 0.062" THK; CLASS: IO; Inventory Qty: 823526; Manufacturer: MILL-MAX; Manufacturer PN: 2501-2-00-80-00-00-07-0; PART_FIELD_01: PGOOD0; PART_NUMBER: 260-0003; Part Number: MILL-MAX 2501-2-00-80-00-00-07-0
E19 = TESTPOINT_.219_MILL-MAX_2501: TEST POINT,TURRET,0.094" MTG. HOLE,PCB 0.062" THK; CLASS: IO; Inventory Qty: 823526; Manufacturer: MILL-MAX; Manufacturer PN: 2501-2-00-80-00-00-07-0; PART_FIELD_01: PGOOD1; PART_NUMBER: 260-0003; Part Number: MILL-MAX 2501-2-00-80-00-00-07-0
E20 = TESTPOINT_.219_MILL-MAX_2501: TEST POINT,TURRET,0.094" MTG. HOLE,PCB 0.062" THK; CLASS: IO; Inventory Qty: 823526; Manufacturer: MILL-MAX; Manufacturer PN: 2501-2-00-80-00-00-07-0; PART_FIELD_01: IOSTEP CLK; PART_NUMBER: 260-0003; Part Number: MILL-MAX 2501-2-00-80-00-00-07-0
J8 = CONN._FCI_12_POS_2MM: CONN.,HDR,SHROUDED,MALE,2x6,2mm,VERT,ST,THT; CLASS: IO; FPLIST: HD2X6-079-MOLEX,AMPHENOL-FCI-9814-X06-12; Inventory Qty: 12768; Manufacturer: AMPHENOL; Manufacturer PN: 98414-G06-12ULF; PART_NUMBER: 250-0433; Part Number: FCI 98414-G06-12ULF
J9 = PMBUS_CON14: CONN.,HDR,MALE,2x7,2mm,R/A THT; CLASS: IO; Inventory Qty: 11393; Manufacturer: MOLEX; Manufacturer PN: 0877601416; PART_NUMBER: 250-0462; Part Number: Molex, LLC 0877601416
J10 = PMBUS_CON14: CONN.,HDR,FEMALE,2x7,2mm,R/A THT; CLASS: IO; Inventory Qty: 10175; Manufacturer: SULLINS CONNECTOR SOLUTIONS; Manufacturer PN: NPPN072FJFN-RC; PART_NUMBER: 250-0461; Part Number: MILL-MAX 803-93-020-20-001
J11 = BNC_50_OHM_112404_B: CONN.,RF,BNC,RCPT,JACK,5-PIN,ST,THT,50 OHMS; 1ST PART FIELD: VOUT0; CLASS: IO; Inventory Qty: 80023; Manufacturer: AMPHENOL RF; Manufacturer PN: 112404; PART_NUMBER: 250-0427; Part Number: AMPHENOL RF 112404
J12 = BNC_50_OHM_112404_B: CONN.,RF,BNC,RCPT,JACK,5-PIN,ST,THT,50 OHMS; 1ST PART FIELD: VOUT1; CLASS: IO; Inventory Qty: 80023; Manufacturer: AMPHENOL RF; Manufacturer PN: 112404; PART_NUMBER: 250-0427; Part Number: AMPHENOL RF 112404
J13 = BNC_50_OHM_112404_B: CONN.,RF,BNC,RCPT,JACK,5-PIN,ST,THT,50 OHMS; 1ST PART FIELD: IOSTEP; CLASS: IO; Inventory Qty: 80023; Manufacturer: AMPHENOL RF; Manufacturer PN: 112404; PART_NUMBER: 250-0427; Part Number: AMPHENOL RF 112404
JP1 = 1X3_A: CONN.,HDR,MALE,1x3,2mm,VERT,ST,THT,NO SUBS. ALLOWED; 10th Part Field: NC; 11th Part Field: C; 9th Part Field: PGOOD0-PGOOD1; CLASS: IO; Inventory Qty: 28997; Manufacturer: Wurth Elektronik; Manufacturer PN: 62000311121; PART_NUMBER: 250-0639; Part Number: Wurth Elektronik 62000311121
JP2 = 1X3_A: CONN.,HDR,MALE,1x3,2mm,VERT,ST,THT,NO SUBS. ALLOWED; 10th Part Field: NC; 11th Part Field: C; 9th Part Field: RUN0-RUN1; CLASS: IO; Inventory Qty: 28997; Manufacturer: Wurth Elektronik; Manufacturer PN: 62000311121; PART_NUMBER: 250-0639; Part Number: Wurth Elektronik 62000311121
JP3 = 1X3_A: CONN.,HDR,MALE,1x3,2mm,VERT,ST,THT,NO SUBS. ALLOWED; 10th Part Field: NC; 11th Part Field: C; 9th Part Field: /FAULT0-/FAULT1; CLASS: IO; Inventory Qty: 28997; Manufacturer: Wurth Elektronik; Manufacturer PN: 62000311121; PART_NUMBER: 250-0639; Part Number: Wurth Elektronik 62000311121
Q2 Q3 = 2N7002_SOT-23: XSTR.,MOSFET,N-CH,60V,300mA,SOT-23-3 (TO-236); CLASS: DISCRETE; Inventory Qty: 6460; Manufacturer: VISHAY; Manufacturer PN: 2N7002K-T1-GE3; PART_NUMBER: 240-0125; Package Size: SOT-23; Package Type: SOT-23-3 (TO-236); Part Number: VISHAY 2N7002K-T1-GE3; Rated Voltage: 60V
Q4 = 3P_N-CH_TYPE2A: XSTR.,MOSFET,N-CH,40V,14A,DPAK (TO-252); CLASS: DISCRETE; Inventory Qty: 44191; Manufacturer: VISHAY; Manufacturer PN: SUD50N04-8M8P-4GE3; PART_NUMBER: 240-0021; Package Type: DPAK (TO-252); Rated Voltage: 40V
R1 = RES: RES.,0 OHM,1/10W,0603,AEC-Q200; CLASS: DISCRETE; FPLIST: CR0603N,CR0603L,CR0603M; Inventory Qty: 680122; Manufacturer: VISHAY; Manufacturer PN: CRCW06030000Z0EA; PART_NUMBER: 100-0009; Package Size: 0603; Part Number: VISHAY CRCW0603200RFKEA; Rated Power: 1/10W
R37 R39 R56 = RES: RES.,10k OHMS,1%,1/10W,0603,AEC-Q200; CLASS: DISCRETE; FPLIST: CR0603N,CR0603L,CR0603M; Inventory Qty: 194448; Manufacturer: VISHAY; Manufacturer PN: CRCW060310K0FKEA; PART_NUMBER: 100-2012; Package Size: 0603; Part Number: VISHAY CRCW060310K0FKEA; Rated Power: 1/10W; Temperature Coefficient: +/-100ppm/C; Tolerance: 1%
R44 R45 = RES: RES.,10 OHMS,5%,1/10W,0603,AEC-Q200; CLASS: DISCRETE; FPLIST: CR0603N,CR0603L,CR0603M; Inventory Qty: 87608; Manufacturer: VISHAY; Manufacturer PN: CRCW060310R0JNEA; PART_NUMBER: 100-2744; Package Size: 0603; Part Number: VISHAY CRCW060310R0JNEA; Rated Power: 1/10W; Temperature Coefficient: +/-200ppm; Tolerance: 5%
R46 R61 = RES: RES.,4.99k OHMS,1%,1/10W,0603,AEC-Q200; CLASS: DISCRETE; FPLIST: CR0603N,CR0603L,CR0603M; Inventory Qty: 89391; Manufacturer: PANASONIC; Manufacturer PN: ERJ3EKF4991V; PART_NUMBER: 100-2510; Package Size: 0603; Part Number: VISHAY CRCW06034K99FKEA; Rated Power: 1/10W; Temperature Coefficient: 100ppm; Tolerance: 1%
R48 = RES: RES., OPTION, 1206; CLASS: DISCRETE; FPLIST: CR1206N,CR1206L,CR1206M; PART_NUMBER: 100-2459; Package Size: 1206
R51 R52 R64-R66 = RES: RES.,866 OHMS,1%,1/10W,0603,AEC-Q200; CLASS: DISCRETE; FPLIST: CR0603N,CR0603L,CR0603M; Inventory Qty: 30000; Manufacturer: VISHAY; Manufacturer PN: CRCW0603866RFKEA; PART_NUMBER: 100-0436; Package Size: 0603; Part Number: VISHAY CRCW0603200RFKEA; Rated Power: 1/10W; Temperature Coefficient: 100ppm; Tolerance: 1%
R53 = RES: RES.,0 OHM,1W,2010,HIGH PWR,PULSE PROOF,AEC-Q200; CLASS: DISCRETE; FPLIST: CR2010N,CR2010L,CR2010M; Inventory Qty: 13195; Manufacturer: VISHAY; Manufacturer PN: CRCW20100000Z0EFHP; PART_NUMBER: 100-2003; Package Size: 2010; Part Number: OPTION; Rated Power: 1W
R54 = RES: RES., OPTION, 2010; CLASS: DISCRETE; FPLIST: CR2010N,CR2010L,CR2010M; PART_NUMBER: 100-2373; Package Size: 2010; Part Number: OPTION
R57 = RES: RES.,0.01 OHM,1%,1W,2512,PWR,METAL,SENSE,AEC-Q200; CLASS: DISCRETE; Inventory Qty: 18659; Manufacturer: VISHAY; Manufacturer PN: WSL2512R0100FEA; PART_NUMBER: 100-0616; Package Size: 2512; Part Number: VISHAY WSL2512R0100FEA; Rated Power: 1W; Temperature Coefficient: 75ppm; Tolerance: 1%
SW1 SW2 = SW-DPDT-JS202011CQN_ALT4: SWITCH,SLIDE,DPDT,0.3A,6VDC,PTH; CLASS: DISCRETE; Inventory Qty: 32171; Manufacturer: C&K; Manufacturer PN: JS202011CQN; PART_NUMBER: 430-0039
U2 = 24LC025-I_ST_TSSOP-8: IC, MEMORY,EEPROM,2Kb (256x8),TSSOP-8,400kHz; CLASS: IC; Inventory Qty: 19510; Manufacturer: Microchip; PART_NUMBER: 380-0087; Package Size: TSSOP-8; Package Type: TSSOP-8; Part Number: MICROCHIP 24LC025-I/ST
U3 = LTC4413-DD: IC,DUAL 2.6A, 2.5V-5.5V IDEAL DIO,10DFN; CLASS: IC; Inventory Qty: 0; Manufacturer: ANALOG DEVICES; Manufacturer PN: LTC4413EDD#PBF; PART_NUMBER: LTC4413EDD#PBF; Package Size: 3mmX3mm; Package Type: 10DFN
U4 = LT1761-S5-X: IC,Low Noise, LDO uPower Reg.,TSOT23-5; CLASS: IC; Inventory Qty: 272; Manufacturer: LINEAR TECH.; Manufacturer PN: LT1761ES5-3.3#PBF; PART_NUMBER: LT1761ES5-3.3#PBF; Package Type: TSOT23-5
LB1 = BLANK_LABEL: LABEL SPEC, DEMO BOARD SERIAL NUMBER; Inventory Qty: 0; Manufacturer: BRADY; Manufacturer PN: THT-96-717-10; PART_NUMBER: 895-0154
MP1-MP4 = BLANK_MECHANICAL_PART: STANDOFF,NYLON,SNAP-ON,0.50"; CLASS: DISCRETE; Inventory Qty: 214842; Manufacturer: KEYSTONE; Manufacturer PN: 8833; PART_NUMBER: 763-0007
PCB1 = BLANK_PCB_PART: BOM Notes: REV04; CLASS: DISCRETE; Inventory Qty: 0; Manufacturer: ADI APPROVED SUPPLIER; Manufacturer PN: 600-DC2836A; PART_NUMBER: 600-DC2836A
STNCL1 = BLANK_STENCIL_PART: BOM Notes: REV04; CLASS: DISCRETE; Inventory Qty: 0; Manufacturer: ADI APPROVED SUPPLIER; Manufacturer PN: 830-DC2836A; PART_NUMBER: 830-DC2836A

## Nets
3V3: C51.1 J8.5(LGKPWR) JP4.1 R40.1 U3.2(~{ENBA}) U3.5(INB)
3V3_LDO: C2.1 C4.1 C50.1 U3.1(INA) U4.5(VOUT)
GND: C1.2 C3.2 C4.2 C5.1 C6.1 C7.1 C8.1 C15.2 C16.2 C17.2 C20.1 C23.2 C24.2 C25.2 C28.1 C29.2 C30.2 C31.2 C32.2 C33.2 C34.2 C35.2 C36.2 C37.2 C38.2 C39.2 C40.2 C41.2 C42.2 C43.2 C44.2 C50.2 C51.2 C52.2 C53.2 C54.2 C55.2 C56.2 C57.1 E2.1 E17.1 E21.1 E42.1(A) E44.1(A) E45.1(A) E47.1 E48.1 J4.1 J6.1 J8.3(GND) J8.10(GND) J9.11(GND) J9.12(GND) J10.11(GND) J10.12(GND) J11.2 J11.3 J11.4 J11.5 J12.2 J12.3 J12.4 J12.5 J13.2 J13.3 J13.4 J13.5 Q2.2 Q3.2 R14.2 R15.2 R16.1 R19.2 R20.2 R21.2 R22.2 R24.2 R25.1 R56.1 R57.2 R67.1 SW1.3 SW2.3 U1.3(SGND) U1.14(PGND) U1.19(PGND) U1.34(PGND) U1.39(PGND) U1.43(GND) U1.44(GND) U1.45(PGND) U1.46(PGND) U1.47(PGND) U1.48(PGND) U2.1(A0) U2.2(A1) U2.3(A2) U2.4(VSS) U2.7(WP) U3.3(GND) U3.4(~{ENBB}) U3.11(GND) U4.2(GND)
VDD18: C6.2 U1.7(VDD18)
VIN0: C3.1 C53.1 C54.1 E41.1(A) L3.2 U1.15(PVIN1) U1.18(PVIN1) U1.35(PVIN0) U1.38(PVIN0)
/ALERT: D6.1(CATHODE) E12.1 J8.6(ALERTB) J9.3(ALERTB) J10.3(ALERTB) R2.1 U1.29(/ALERT)
/FAULT0: D7.1(CATHODE) JP3.3 R4.1 U1.28(/FAULT0)
/FAULT1: D8.1(CATHODE) JP3.1 JP3.2 R3.1 U1.27(/FAULT1)
AUXVCC: C31.1 J8.1(AUXP) J9.8(AUXP) J10.8(AUXP) R46.1 R61.1 U2.8(VCC)
BOOST0: C14.1 U1.40(BOOST0)
BOOST1: C22.1 U1.13(BOOST1)
DRVCC: C5.2 U1.20(DRVCC)
EESCL: J8.11(AUXSCL) R46.2 U2.6(SCL)
EESDA: J8.12(AUXSDA) R61.2 U2.5(SDA)
EXTVCC: C7.2 C57.2 E40.1 JP4.2 R62.1 U1.21(EXTVCC)
INTVCC: C8.2 R12.1 R23.1 U1.6(INTVCC)
ITH0: C19.2 C20.2 R12.2 R26.1 U1.4(ITH0)
ITH1: C27.2 C28.2 R23.2 R26.2 U1.5(ITH1)
PGOOD0: D2.2(A) E18.1 JP1.3 Q2.1 R5.1 R35.2 R36.2 U1.33(PGOOD0)
PGOOD1: D1.2(A) E19.1 JP1.1 JP1.2 Q3.1 R6.1 R33.2 R34.2 U1.32(PGOOD1)
RUN0: D2.1(C) JP2.3 R34.1 R37.2 R38.2 R45.2 SW1.1 SW1.2 U1.24(RUN0)
RUN1: D1.1(C) JP2.1 JP2.2 R36.1 R39.2 R43.2 R44.2 SW2.1 SW2.2 U1.23(RUN1)
SCL: E14.1 J8.4(SCL) J9.6(SCL) J10.6(SCL) R9.1 U1.30(SCL)
SDA: E13.1 J8.2(SDA) J9.4(SDA) J10.4(SDA) R8.1 U1.31(SDA)
SHARE_CLK: E15.1 R7.1 R41.1 R67.2 U1.25(SHARE_CLK)
SYNC: R21.1 R42.1 R63.2 U1.22(SYNC/PWM_CFG)
VEMI: C38.1 C39.1 C43.1 C44.1 E1.1 FB1.1 R1.1 R48.1
VOUT0: C15.1 C16.1 C17.1 C32.1 C36.1 C55.1 E43.1(A) J3.1 J11.1 L1.2 R11.1 R29.2 R30.2 R53.2
VOUT1: C23.1 C24.1 C25.1 C33.1 C37.1 C56.1 E46.1(A) J5.1 J12.1 L2.2 R18.1 R29.1 R30.1 R54.1 R62.2
VPULLUP: C52.1 R2.2 R3.2 R4.2 R5.2 R6.2 R7.2 R8.2 R9.2 R13.2 R37.1 R39.1 R51.1 R52.1 R64.1 R65.1 R66.1 U3.6(OUTB) U3.10(OUTA)
VSENSE0+: R11.2 R27.1 U1.2(VSENSE0P)
VSENSE0-: R16.2 R28.1 U1.1(VSENSE0N)
VSENSE1+: R18.2 R27.2 U1.11(VSENSE1P)
VSENSE1-: R25.2 R28.2 U1.12(VSENSE1N)
X00001: C14.2 L1.1 U1.36(SW0) U1.37(SW0) U1.41(SW0)
X00002: C22.2 L2.1 U1.16(SW1) U1.17(SW1) U1.42(SW1)
N20908893: C19.1 R15.1
N20910533: R22.1 U1.10(ASEL)
N20914200: J9.1(FAULTB) J10.1(FAULTB) R33.1 R35.1
N20914234: J9.2(CTRL) J10.2(CTRL) R38.1 R43.1 R49.2 R50.2
N20914347: J9.9(UNUSED) J10.9(UNUSED) R42.2
N20914417: J8.8(OUTEN_0) R49.1
N20914674: J8.9(OUTEN_1) R50.1
N20914708: J9.13(12V) J9.14(12V) J10.13(12V) J10.14(12V) R48.2
N20914860: J9.10(UNUSED) J10.10(UNUSED) R40.2
N20915030: C29.1 R44.1
N20915135: J9.7(RESETB) J10.7(RESETB)
N20923371: J13.1 Q4.3(S) R57.1
N20923421: E20.1 Q4.1(G) R56.2
N20923454: C34.1 C35.1 Q4.2(D) R53.1 R54.2
N20951080: D5.1(CATHODE) Q3.3
N20952274: D4.1(CATHODE) Q2.3
N21023994: C40.1 C41.1 C42.1 FB1.2 L3.1
N21117354: R13.1 R14.1 U1.26(WP)
N21117863: R19.1 U1.8(VOUT0_CFG)
N21118140: R20.1 U1.9(VOUT1_CFG)
N21132662: C27.1 R24.1
N21135003: E16.1 R63.1
N21135199: J9.5(SHARE_CLK) J10.5(SHARE_CLK) R41.2
N21141698: D6.2(ANODE) R64.2
N21141762: D4.2(ANODE) R51.2
N21141776: D5.2(ANODE) R52.2
N21148484: D8.2(ANODE) R65.2
N21148647: D7.2(ANODE) R66.2
N21189372: C30.1 R45.1
N21232530: C1.1 R1.2 U4.1(IN) U4.3(~{SHDN})
N21232573: C2.2 U4.4(BYP)

Not connected (* = marked no-connect by the designer): J8 7(GPIO_1)*; JP4 3*; SW1 4 5 6; SW2 4 5 6; U3 7(NC)* 8(NC)* 9(STAT)*

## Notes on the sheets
sheet 2
- Optional Resistors for Single Output Configuration
- 2
- 2
- 2
- 2
- 2
- NOTE: UNLESS OTHERWISE SPECIFIED
- 1.  ALL RESISTORS AND CAPACITORS ARE 0603.
- 2   FOR SINGLE OUTPUT CONFIGURATION.
- NOTE:
  T1 - T8 ARE EXPOSED PCB VIAS
  FOR USE AS TEST POINTS
- NOTE:
  VOUT0 AND VOUT1 DEFAULT OUTPUT = 1.8V
- LTC3880EUJ - CURRENT MODE DUAL PHASE / DUAL CHANNEL
  STEP-DOWN CONTROLLER WITH I2C / PMBus INTERFACE
- MAKE ALL SENSE CONNECTIONS TO L1/L2
  AND R10/R16 DIFFERENTIAL AND KELVIN
sheet 3
- ALL PARTS ON THIS PAGE ARE FOR DEMO ONLY, NOT NEEDED IN CUSTOMER DESIGN
- ON
- ON
- TO DC1613A
- OFF
- OFF
- RUN1
- RUN0
- 1206
- LOAD TRANSIENT CIRCUIT
- NOTE: UNLESS OTHERWISE SPECIFIED
- 1.  ALL RESISTORS AND CAPACITORS ARE 0603.
- 2   FOR SINGLE OUTPUT CONFIGURATION.
